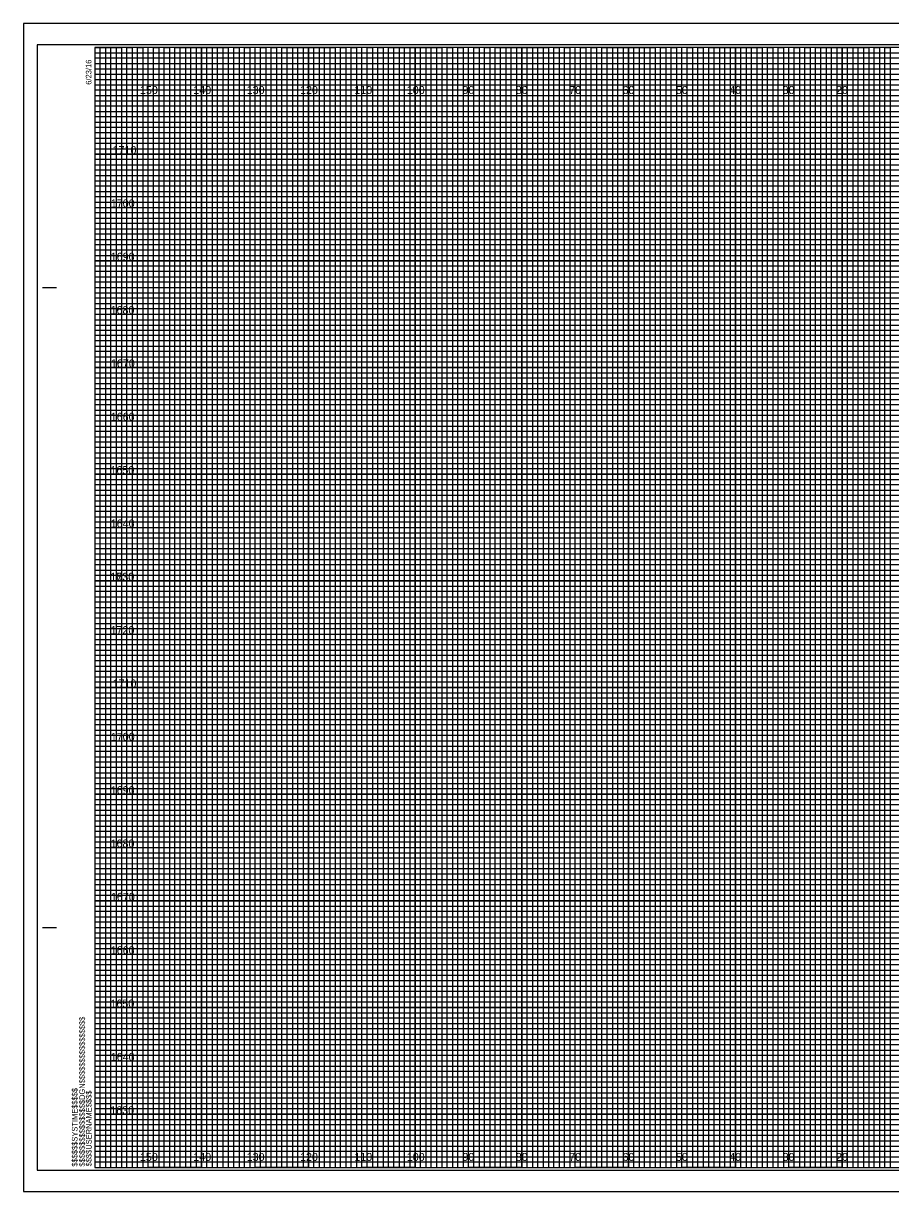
# Model space of a CAD drawing. Extents: x -419 to 4739, y -630 to 13534.
# Drawn here: x 1539.8 to 1702.3, y 415.2 to 634.2 of the extents above; entities that cross this region are included whole.
import ezdxf

# ---------------------------------------------------------------- set-up
doc = ezdxf.new("R2010")
doc.units = 0
for name, color, linetype in [('Old_Level_62', 7, 'Continuous'), ('Pattern 1', 7, 'Continuous'), ('Pattern 18', 7, 'Continuous'), ('Pattern 4', 7, 'Continuous'), ('Pattern 5', 7, 'Continuous'), ('Prop Dimension', 7, 'Continuous'), ('Prop Horizontal Alignment', 7, 'Continuous'), ('Raster_Level_0', 7, 'Continuous'), ('Scratch_Level_0', 7, 'Continuous'), ('Scratch_Level_3', 7, 'Continuous'), ('Scratch_Level_5', 7, 'Continuous')]:
    doc.layers.add(name, color=color, linetype=linetype)

msp = doc.modelspace()

# ---------------------------------------------------------------- linework, layer by layer
at = {"layer": 'Old_Level_62'}
for p, q in [((1543.4, 584.66), (1545.9, 584.66)), ((1543.5, 584.66), (1546, 584.66)), ((1543.4, 464.66), (1545.9, 464.66)), ((1543.5, 464.66), (1546, 464.66)), ((1553.2, 419.66), (1553.2, 419.66)), ((1553.2, 419.66), (1553.2, 419.66)), ((1553.2, 419.66), (1553.2, 419.66)), ((1553.2, 419.66), (1553.2, 419.66)), ((1553.2, 419.66), (1553.2, 419.66)), ((1553.2, 419.66), (1553.2, 419.66)), ((1553.2, 419.66), (1553.2, 419.66))]:
    msp.add_line(p, q, dxfattribs=at)
msp.add_lwpolyline([(1873.2, 629.66), (1553.2, 629.66), (1553.2, 419.66), (1873.2, 419.66)], close=True, dxfattribs=at)
at = {"layer": 'Pattern 18'}
msp.add_lwpolyline([(1539.8, 415.16), (1876.5, 415.16), (1876.5, 634.16), (1539.8, 634.16)], close=True, dxfattribs=at)
at = {"layer": 'Pattern 4'}
for p, q in [((1553.2, 628.66), (1813.2, 628.66)), ((1813.2, 627.64), (1553.2, 627.64)), ((1553.2, 627.64), (1553.2, 626.66)), ((1553.2, 626.66), (1813.2, 626.66)), ((1813.2, 625.55), (1553.2, 625.55)), ((1553.2, 625.55), (1553.2, 623.66)), ((1553.2, 623.66), (1873.2, 623.66))]:
    msp.add_line(p, q, dxfattribs=at)
for points in [[(1553.2, 622.66), (1823.2, 622.66), (1873.2, 622.66), (1873.2, 621.66), (1553.2, 621.66)], [(1553.2, 620.66), (1873.2, 620.66), (1873.2, 618.66), (1553.2, 618.66)], [(1553.2, 617.66), (1873.2, 617.66), (1873.2, 616.66), (1553.2, 616.64)], [(1553.2, 615.66), (1873.2, 615.66), (1873.2, 613.66), (1553.2, 613.66)], [(1553.2, 612.66), (1873.2, 612.66), (1873.2, 611.66), (1553.2, 611.66)], [(1553.2, 610.66), (1873.2, 610.66), (1873.2, 608.66), (1553.2, 608.66)], [(1553.2, 607.66), (1873.2, 607.66), (1873.2, 606.66), (1553.2, 606.66)], [(1553.2, 605.66), (1873.2, 605.66), (1873.2, 603.66), (1553.2, 603.66)], [(1553.2, 602.66), (1873.2, 602.66), (1873.2, 601.66), (1553.2, 601.66)], [(1553.2, 600.66), (1873.2, 600.66), (1873.2, 598.66), (1553.2, 598.66)], [(1553.2, 597.66), (1873.2, 597.66), (1873.2, 596.66), (1553.2, 596.66)], [(1553.2, 595.66), (1873.2, 595.66), (1873.2, 593.61), (1873.2, 592.66), (1873.2, 591.66), (1553.2, 591.66)], [(1553.2, 593.66), (1873.2, 593.66), (1873.2, 592.66), (1553.2, 592.66)], [(1553.2, 590.66), (1873.2, 590.66), (1873.2, 588.66), (1553.2, 588.69)], [(1553.2, 588.69), (1873.2, 588.66), (1873.2, 587.66), (1553.2, 587.66)], [(1553.2, 586.66), (1873.2, 586.66), (1873.2, 585.66), (1553.2, 585.66)], [(1553.2, 583.66), (1873.2, 583.66), (1873.2, 582.66), (1553.2, 582.66)], [(1553.2, 581.66), (1873.2, 581.66), (1873.2, 580.66), (1553.2, 580.66)], [(1553.13, 578.55), (1873.2, 578.55), (1873.2, 577.54), (1553.13, 577.54)], [(1553.2, 576.66), (1873.2, 576.66), (1873.2, 575.66), (1553.2, 575.66)], [(1553.2, 573.66), (1873.2, 573.66), (1873.2, 572.66), (1553.2, 572.66)], [(1553.2, 571.66), (1873.2, 571.66), (1873.2, 570.66), (1553.2, 570.66)], [(1553.2, 568.66), (1873.2, 568.66), (1873.2, 567.66), (1553.2, 567.66)], [(1553.2, 566.66), (1873.2, 566.66), (1873.2, 565.66), (1553.2, 565.66)], [(1553.2, 563.66), (1873.2, 563.66), (1873.2, 562.66), (1553.2, 562.66)], [(1553.2, 561.66), (1873.2, 561.66), (1873.2, 560.66), (1553.2, 560.66)], [(1553.2, 558.66), (1873.2, 558.66), (1873.19, 557.64), (1553.2, 557.66)], [(1553.2, 556.66), (1873.2, 556.66), (1873.2, 555.66), (1553.2, 555.66)], [(1553.2, 553.66), (1873.2, 553.66), (1873.2, 552.66), (1553.2, 552.66)], [(1553.2, 551.66), (1873.2, 551.66), (1873.2, 550.66), (1553.2, 550.66)], [(1553.2, 548.66), (1873.2, 548.66), (1873.2, 547.66), (1553.2, 547.66)], [(1553.2, 546.66), (1873.2, 546.66), (1873.2, 545.66), (1553.2, 545.66)], [(1553.2, 543.66), (1873.2, 543.66), (1873.2, 542.66), (1553.2, 542.66)], [(1553.2, 541.66), (1873.2, 541.66), (1873.2, 540.66), (1553.2, 540.66)], [(1553.2, 538.66), (1873.2, 538.66), (1873.2, 537.66), (1553.2, 537.66)], [(1553.2, 536.65), (1873.27, 536.57), (1873.2, 535.66), (1553.2, 535.66)], [(1553.2, 533.66), (1873.2, 533.66), (1873.2, 532.66), (1553.2, 532.66)], [(1553.2, 531.66), (1873.2, 531.66), (1873.2, 530.66), (1553.2, 530.66)], [(1553.2, 528.66), (1873.2, 528.66), (1873.2, 527.66), (1553.2, 527.66)], [(1553.2, 526.66), (1873.2, 526.66), (1873.2, 525.66), (1553.2, 525.66)], [(1553.2, 523.66), (1873.2, 523.66), (1873.2, 522.66), (1553.2, 522.66)], [(1553.2, 521.66), (1873.2, 521.66), (1873.2, 520.66), (1553.2, 520.66)], [(1553.2, 518.66), (1873.2, 518.66), (1873.2, 517.66), (1553.2, 517.66)], [(1553.2, 516.66), (1873.2, 516.66), (1873.2, 515.66), (1553.2, 515.66)], [(1553.2, 513.66), (1873.2, 513.66), (1873.2, 512.66), (1553.2, 512.66)], [(1553.2, 511.66), (1873.2, 511.66), (1873.2, 510.66), (1553.2, 510.66)], [(1553.2, 508.66), (1873.2, 508.66), (1873.2, 507.66), (1553.2, 507.66)], [(1553.2, 506.66), (1873.2, 506.66), (1873.2, 505.66), (1553.2, 505.66)], [(1553.2, 503.66), (1873.2, 503.66), (1873.2, 502.66), (1553.2, 502.66)], [(1553.2, 501.66), (1873.2, 501.66), (1873.2, 500.66), (1553.2, 500.66)], [(1553.2, 498.66), (1873.2, 498.66), (1873.19, 497.64), (1553.2, 497.66)], [(1553.2, 496.66), (1873.2, 496.66), (1873.2, 495.66), (1553.2, 495.66)], [(1553.2, 493.66), (1873.2, 493.66), (1873.2, 492.66), (1553.2, 492.66)], [(1553.2, 491.66), (1873.2, 491.66), (1873.2, 490.66), (1553.2, 490.66)], [(1553.2, 488.66), (1873.2, 488.66), (1873.2, 487.66), (1553.2, 487.66)], [(1553.2, 486.66), (1873.2, 486.66), (1873.2, 485.66), (1553.2, 485.66)], [(1553.2, 483.66), (1873.2, 483.66), (1873.2, 482.66), (1553.2, 482.66)], [(1553.2, 481.66), (1873.2, 481.66), (1873.2, 480.66), (1553.2, 480.66)], [(1553.2, 478.66), (1873.2, 478.66), (1873.2, 477.66), (1553.2, 477.66)], [(1553.2, 476.65), (1873.27, 476.57), (1873.2, 475.66), (1553.2, 475.66)], [(1553.2, 473.66), (1873.2, 473.66), (1873.2, 472.66), (1553.2, 472.66)], [(1553.2, 471.66), (1873.2, 471.66), (1873.2, 470.66), (1553.2, 470.66)], [(1553.2, 468.66), (1873.2, 468.66), (1873.2, 467.66), (1553.2, 467.66)], [(1553.2, 466.66), (1873.2, 466.66), (1873.2, 465.66), (1553.2, 465.66)], [(1553.2, 463.66), (1873.2, 463.66), (1873.2, 462.66), (1553.2, 462.66)], [(1553.2, 461.66), (1873.2, 461.66), (1873.2, 460.66), (1553.2, 460.66)], [(1553.2, 458.66), (1873.2, 458.66), (1873.2, 457.66), (1553.2, 457.66)], [(1553.2, 456.66), (1873.2, 456.66), (1873.2, 455.66), (1553.2, 455.66)], [(1553.2, 453.66), (1873.2, 453.66), (1873.2, 452.66), (1553.2, 452.66)], [(1553.2, 451.66), (1873.2, 451.66), (1873.2, 450.66), (1553.2, 450.66)], [(1553.2, 448.66), (1873.2, 448.66), (1873.2, 447.66), (1553.2, 447.66)], [(1553.2, 446.66), (1873.2, 446.66), (1873.2, 445.66), (1553.2, 445.66)], [(1553.2, 443.66), (1873.2, 443.66), (1873.2, 442.66), (1553.2, 442.66)], [(1553.2, 441.66), (1873.2, 441.66), (1873.2, 440.66), (1553.2, 440.66)], [(1553.2, 438.66), (1873.2, 438.66), (1873.2, 437.66), (1553.2, 437.66)], [(1553.2, 436.66), (1873.2, 436.66), (1873.2, 435.66), (1553.2, 435.66)], [(1553.2, 433.66), (1873.2, 433.66), (1873.2, 432.66), (1553.2, 432.66)], [(1553.2, 431.66), (1873.2, 431.66), (1873.2, 430.66), (1553.2, 430.66)], [(1553.2, 428.66), (1873.2, 428.66), (1873.2, 427.66), (1553.2, 427.66)], [(1553.2, 426.66), (1873.2, 426.66), (1873.2, 425.66), (1553.2, 425.66)], [(1553.2, 423.66), (1873.2, 423.66), (1873.2, 422.66), (1553.2, 422.66)], [(1553.2, 421.66), (1873.2, 421.66), (1873.2, 420.66), (1553.2, 420.66)]]:
    msp.add_lwpolyline(points, dxfattribs=at)
at = {"layer": 'Pattern 5'}
for p, q in [((1876.5, 634.16), (1539.8, 634.16)), ((1539.8, 634.16), (1539.8, 415.16)), ((1539.8, 415.16), (1876.5, 415.16))]:
    msp.add_line(p, q, dxfattribs=at)
at = {"layer": 'Prop Dimension'}
for points in [[(1553.2, 419.66), (1554.2, 419.66), (1554.2, 629.66), (1555.2, 629.66), (1555.2, 419.66)], [(1555.2, 419.66), (1556.2, 419.66), (1556.2, 629.66), (1557.2, 629.66), (1557.2, 419.66)], [(1558.2, 419.66), (1559.2, 419.66), (1559.2, 629.66), (1560.2, 629.66), (1560.2, 419.66)], [(1560.2, 419.66), (1561.2, 419.66), (1561.2, 629.66), (1562.2, 629.66), (1562.2, 419.66)], [(1563.2, 419.66), (1564.2, 419.66), (1564.2, 629.66), (1565.2, 629.66), (1565.2, 419.66)], [(1565.2, 419.66), (1566.2, 419.66), (1566.2, 629.66), (1567.2, 629.66), (1567.2, 419.66)], [(1568.2, 419.66), (1569.2, 419.66), (1569.2, 629.66), (1570.2, 629.66), (1570.2, 419.66)], [(1570.2, 419.66), (1571.2, 419.66), (1571.2, 629.66), (1572.2, 629.66), (1572.2, 419.66)], [(1573.2, 419.66), (1574.2, 419.66), (1574.2, 629.66), (1575.2, 629.66), (1575.2, 419.66)], [(1575.2, 419.66), (1576.2, 419.66), (1576.2, 629.66), (1577.2, 629.66), (1577.2, 419.66)], [(1578.2, 419.66), (1579.2, 419.66), (1579.2, 629.66), (1580.2, 629.66), (1580.2, 419.66)], [(1580.2, 419.66), (1581.2, 419.66), (1581.2, 629.66), (1582.2, 629.66), (1582.2, 419.66)], [(1583.2, 419.66), (1584.2, 419.66), (1584.2, 629.66), (1585.2, 629.66), (1585.2, 419.66)], [(1585.2, 419.66), (1586.2, 419.66), (1586.2, 629.66), (1587.2, 629.66), (1587.2, 419.66)], [(1588.2, 419.66), (1589.2, 419.66), (1589.2, 629.66), (1590.2, 629.66), (1590.2, 419.66)], [(1590.2, 419.66), (1591.2, 419.66), (1591.2, 629.66), (1592.2, 629.66), (1592.2, 419.66)], [(1593.2, 419.66), (1594.2, 419.66), (1594.2, 629.66), (1595.2, 629.66), (1595.2, 419.66)], [(1595.2, 419.66), (1596.2, 419.66), (1596.2, 629.66), (1597.2, 629.66), (1597.2, 419.66)], [(1598.2, 419.66), (1599.2, 419.66), (1599.2, 629.66), (1600.2, 629.66), (1600.2, 419.66)], [(1600.2, 419.66), (1601.2, 419.66), (1601.2, 629.66), (1602.2, 629.66), (1602.2, 419.66)], [(1603.2, 419.66), (1604.2, 419.66), (1604.2, 629.66), (1605.2, 629.66), (1605.2, 419.66)], [(1605.2, 419.66), (1606.2, 419.66), (1606.2, 629.66), (1607.2, 629.66), (1607.2, 419.66)], [(1608.2, 419.66), (1609.2, 419.66), (1609.2, 629.66), (1610.2, 629.66), (1610.2, 419.66)], [(1610.2, 419.66), (1611.2, 419.66), (1611.2, 629.66), (1612.2, 629.66), (1612.2, 419.66)], [(1613.2, 419.66), (1614.2, 419.66), (1614.2, 629.66), (1615.2, 629.66), (1615.2, 419.66)], [(1615.2, 419.66), (1616.2, 419.66), (1616.2, 629.66), (1617.2, 629.66), (1617.2, 419.66)], [(1618.2, 419.66), (1619.2, 419.66), (1619.2, 629.66), (1620.2, 629.66), (1620.2, 419.66)], [(1620.2, 419.66), (1621.2, 419.66), (1621.2, 629.66), (1622.2, 629.66), (1622.2, 419.66)], [(1623.2, 419.66), (1624.2, 419.66), (1624.2, 629.66), (1625.2, 629.66), (1625.2, 419.66)], [(1625.2, 419.66), (1626.2, 419.66), (1626.2, 629.66), (1627.2, 629.66), (1627.2, 419.66)], [(1628.2, 419.66), (1629.2, 419.66), (1629.2, 629.66), (1630.2, 629.66), (1630.2, 419.66)], [(1630.2, 419.66), (1631.2, 419.66), (1631.2, 629.66), (1632.2, 629.66), (1632.2, 419.66)], [(1633.2, 419.66), (1634.2, 419.66), (1634.2, 629.66), (1635.2, 629.66), (1635.2, 419.66)], [(1635.2, 419.66), (1636.2, 419.66), (1636.2, 629.66), (1637.2, 629.66), (1637.2, 419.66)], [(1638.2, 419.66), (1639.2, 419.66), (1639.2, 629.66), (1640.2, 629.66), (1640.2, 419.66)], [(1640.2, 419.66), (1641.2, 419.66), (1641.2, 629.66), (1642.2, 629.66), (1642.2, 419.66)], [(1643.2, 419.66), (1644.2, 419.66), (1644.2, 629.66), (1645.2, 629.66), (1645.2, 419.66)], [(1645.2, 419.66), (1646.2, 419.66), (1646.2, 629.66), (1647.2, 629.66), (1647.2, 419.66)], [(1648.2, 419.66), (1649.2, 419.66), (1649.2, 629.66), (1650.2, 629.66), (1650.2, 419.66)], [(1650.2, 419.66), (1651.2, 419.66), (1651.2, 629.66), (1652.2, 629.66), (1652.2, 419.66)], [(1653.2, 419.66), (1654.2, 419.66), (1654.2, 629.66), (1655.2, 629.66), (1655.2, 419.66)], [(1655.2, 419.66), (1656.2, 419.66), (1656.2, 629.66), (1657.2, 629.66), (1657.2, 419.66)], [(1658.2, 419.66), (1659.2, 419.66), (1659.2, 629.66), (1660.2, 629.66), (1660.2, 419.66)], [(1660.2, 419.66), (1661.2, 419.66), (1661.2, 629.66), (1662.2, 629.66), (1662.2, 419.66)], [(1663.2, 419.66), (1664.2, 419.66), (1664.2, 629.66), (1665.2, 629.66), (1665.2, 419.66)], [(1665.2, 419.66), (1666.2, 419.66), (1666.2, 629.66), (1667.2, 629.66), (1667.2, 419.66)], [(1668.2, 419.66), (1669.2, 419.66), (1669.2, 629.66), (1670.2, 629.66), (1670.2, 419.66)], [(1670.2, 419.66), (1671.2, 419.66), (1671.2, 629.66), (1672.2, 629.66), (1672.2, 419.66)], [(1673.2, 419.66), (1674.2, 419.66), (1674.2, 629.66), (1675.2, 629.66), (1675.2, 419.66)], [(1675.2, 419.66), (1676.2, 419.66), (1676.2, 629.66), (1677.2, 629.66), (1677.2, 419.66)], [(1678.2, 419.66), (1679.2, 419.66), (1679.2, 629.66), (1680.2, 629.66), (1680.2, 419.66)], [(1680.2, 419.66), (1681.2, 419.66), (1681.2, 629.66), (1682.2, 629.66), (1682.2, 419.66)], [(1683.2, 419.66), (1684.2, 419.66), (1684.2, 629.66), (1685.2, 629.66), (1685.2, 419.66)], [(1685.2, 419.66), (1686.2, 419.66), (1686.2, 629.66), (1687.2, 629.66), (1687.2, 419.66)], [(1688.2, 419.66), (1689.2, 419.66), (1689.2, 629.66), (1690.2, 629.66), (1690.2, 419.66)], [(1690.2, 419.66), (1691.2, 419.66), (1691.2, 629.66), (1692.2, 629.66), (1692.2, 419.66)], [(1693.2, 419.66), (1694.2, 419.66), (1694.2, 629.66), (1695.2, 629.66), (1695.2, 419.66)], [(1695.2, 419.66), (1696.2, 419.66), (1696.2, 629.66), (1697.2, 629.66), (1697.2, 419.66)], [(1698.2, 419.66), (1699.2, 419.66), (1699.2, 629.66), (1700.2, 629.66), (1700.2, 419.66)], [(1700.2, 419.66), (1701.2, 419.66), (1701.2, 629.66), (1702.2, 629.66), (1702.2, 419.66)]]:
    msp.add_lwpolyline(points, dxfattribs=at)
at = {"layer": 'Prop Horizontal Alignment'}
for points in [[(1553.2, 629.66), (1558.2, 629.66), (1558.2, 419.66), (1568.2, 419.66), (1568.2, 629.66), (1578.2, 629.66), (1578.2, 419.66), (1588.2, 419.66), (1588.2, 629.66), (1598.2, 629.66), (1598.2, 419.66), (1608.2, 419.66), (1608.2, 629.66), (1618.2, 629.66), (1618.2, 419.66), (1628.2, 419.66), (1628.2, 629.66), (1638.2, 629.66), (1638.2, 419.66), (1648.2, 419.66), (1648.2, 629.66), (1658.2, 629.66), (1658.2, 419.66), (1668.2, 419.66), (1668.2, 629.66), (1678.2, 629.66), (1678.2, 419.66), (1688.2, 419.66), (1688.2, 629.66), (1698.2, 629.66), (1698.2, 419.66), (1708.2, 419.66)], [(1553.2, 624.66), (1828.2, 624.66)], [(1553.2, 604.66), (1873.2, 604.66), (1873.2, 614.66), (1553.2, 614.66)], [(1553.2, 584.66), (1873.2, 584.66), (1873.2, 594.66), (1553.2, 594.66)], [(1553.2, 564.66), (1873.2, 564.66), (1873.2, 574.66), (1553.2, 574.66)], [(1553.2, 544.66), (1873.2, 544.66), (1873.2, 554.66), (1553.2, 554.66)], [(1553.2, 524.66), (1873.2, 524.66), (1873.2, 534.66), (1553.2, 534.66)], [(1553.2, 504.66), (1873.2, 504.66), (1873.2, 514.66), (1553.2, 514.66)], [(1553.2, 484.66), (1873.2, 484.66), (1873.2, 494.66), (1553.2, 494.66)], [(1553.2, 464.66), (1873.2, 464.66), (1873.2, 474.66), (1553.2, 474.66)], [(1553.2, 444.66), (1873.2, 444.66), (1873.2, 454.66), (1553.2, 454.66)], [(1553.2, 424.66), (1873.2, 424.66), (1873.2, 434.66), (1553.2, 434.66)]]:
    msp.add_lwpolyline(points, dxfattribs=at)
at = {"layer": 'Scratch_Level_0'}
for p, q in [((1563.2, 419.66), (1563.2, 629.66)), ((1573.2, 419.66), (1573.2, 629.66)), ((1583.2, 419.66), (1583.2, 629.66)), ((1593.2, 419.66), (1593.2, 629.66)), ((1603.2, 419.66), (1603.2, 629.66)), ((1613.2, 419.66), (1613.2, 629.66)), ((1623.2, 419.66), (1623.2, 629.66)), ((1633.2, 419.66), (1633.2, 629.66)), ((1643.2, 419.66), (1643.2, 629.66)), ((1653.2, 419.66), (1653.2, 629.66)), ((1663.2, 419.66), (1663.2, 629.66)), ((1673.2, 419.66), (1673.2, 629.66)), ((1683.2, 419.66), (1683.2, 629.66)), ((1693.2, 419.66), (1693.2, 629.66)), ((1553.2, 619.66), (1873.2, 619.66)), ((1553.2, 609.66), (1873.2, 609.66)), ((1553.2, 599.66), (1873.2, 599.66)), ((1553.2, 589.66), (1873.2, 589.66)), ((1553.2, 579.66), (1873.2, 579.66)), ((1553.2, 569.66), (1873.2, 569.66)), ((1553.2, 559.66), (1873.2, 559.66)), ((1553.2, 549.66), (1873.2, 549.66)), ((1553.2, 539.66), (1873.2, 539.66)), ((1553.2, 529.66), (1873.2, 529.66)), ((1553.2, 519.66), (1873.2, 519.66)), ((1553.2, 509.66), (1873.2, 509.66)), ((1553.2, 499.66), (1873.2, 499.66)), ((1553.2, 489.66), (1873.2, 489.66)), ((1553.2, 479.66), (1873.2, 479.66)), ((1553.2, 469.66), (1873.2, 469.66)), ((1553.2, 459.66), (1873.2, 459.66)), ((1553.2, 449.66), (1873.2, 449.66)), ((1553.2, 439.66), (1873.2, 439.66)), ((1553.2, 429.66), (1873.2, 429.66))]:
    msp.add_line(p, q, dxfattribs=at)
at = {"layer": 'Scratch_Level_3'}
for p, q in [((1563.2, 629.66), (1553.2, 629.66)), ((1563.2, 419.66), (1563.2, 629.66)), ((1583.2, 629.66), (1573.2, 629.66)), ((1573.2, 629.66), (1573.2, 419.66)), ((1583.2, 419.66), (1583.2, 629.66)), ((1603.2, 629.66), (1593.2, 629.66)), ((1593.2, 629.66), (1593.2, 419.66)), ((1603.2, 419.66), (1603.2, 629.66)), ((1623.2, 629.66), (1613.2, 629.66)), ((1613.2, 629.66), (1613.2, 419.66)), ((1623.2, 419.66), (1623.2, 629.66)), ((1643.2, 629.66), (1633.2, 629.66)), ((1633.2, 629.66), (1633.2, 419.66)), ((1643.2, 419.66), (1643.2, 629.66)), ((1663.2, 629.66), (1653.2, 629.66)), ((1653.2, 629.66), (1653.2, 419.66)), ((1663.2, 419.66), (1663.2, 629.66)), ((1683.2, 629.66), (1673.2, 629.66)), ((1673.2, 629.66), (1673.2, 419.66)), ((1683.2, 419.66), (1683.2, 629.66)), ((1703.2, 629.66), (1693.2, 629.66)), ((1693.2, 629.66), (1693.2, 419.66)), ((1573.2, 419.66), (1563.2, 419.66)), ((1593.2, 419.66), (1583.2, 419.66)), ((1613.2, 419.66), (1603.2, 419.66)), ((1633.2, 419.66), (1623.2, 419.66)), ((1653.2, 419.66), (1643.2, 419.66)), ((1673.2, 419.66), (1663.2, 419.66)), ((1693.2, 419.66), (1683.2, 419.66))]:
    msp.add_line(p, q, dxfattribs=at)
for points in [[(1553.2, 619.66), (1873.2, 619.66), (1873.2, 609.66), (1553.2, 609.66)], [(1553.2, 599.66), (1873.2, 599.66), (1873.2, 589.66), (1553.2, 589.66)], [(1553.2, 579.66), (1873.2, 579.66), (1873.2, 569.66), (1553.2, 569.66)], [(1553.2, 559.66), (1873.2, 559.66), (1873.2, 549.66), (1553.2, 549.66)], [(1553.2, 539.66), (1873.2, 539.66), (1873.2, 529.66), (1553.2, 529.66)], [(1553.2, 519.66), (1873.2, 519.66), (1873.2, 509.66), (1553.2, 509.66)], [(1553.2, 499.66), (1873.2, 499.66), (1873.2, 489.66), (1553.2, 489.66)], [(1553.2, 479.66), (1873.2, 479.66), (1873.2, 469.66), (1553.2, 469.66)], [(1553.2, 459.66), (1873.2, 459.66), (1873.2, 449.66), (1553.2, 449.66)], [(1553.2, 439.66), (1873.2, 439.66), (1873.2, 429.66), (1553.2, 429.66)]]:
    msp.add_lwpolyline(points, dxfattribs=at)
at = {"layer": 'Scratch_Level_5'}
msp.add_lwpolyline([(1542.4, 419.16), (1875.6, 419.16), (1875.6, 630.16), (1542.4, 630.16)], close=True, dxfattribs=at)

# ---------------------------------------------------------------- texts
at = {"layer": 'Old_Level_62'}
for s, p in [('6/23/16', (1552.55, 622.66)), ('$$$$$$$$$$$$$$$$DGN$$$$$$$$$$$$$$$$', (1551.32, 419.84)), ('$$$$$$SYSTIME$$$$$', (1549.94, 419.84)), ('$$$$USERNAME$$$$', (1552.58, 419.89))]:
    msp.add_text(s, height=1.05, rotation=90, dxfattribs=at).set_placement(p)
at = {"layer": 'Pattern 1'}
for s, p in [('1710', (1556.51, 609.66)), ('1700', (1556.18, 599.66)), ('1690', (1556.17, 589.66)), ('1680', (1556.14, 579.66)), ('1670', (1556.2, 569.66)), ('1660', (1556.17, 559.66)), ('1650', (1556.12, 549.66)), ('1640', (1556.17, 539.66)), ('1630', (1556.08, 529.66)), ('1730', (1556.12, 529.66)), ('1720', (1556.13, 519.66)), ('1710', (1556.51, 509.66)), ('1700', (1556.18, 499.66)), ('1690', (1556.17, 489.66)), ('1680', (1556.14, 479.66)), ('1670', (1556.2, 469.66)), ('1660', (1556.17, 459.66)), ('1650', (1556.12, 449.66)), ('1640', (1556.17, 439.66)), ('1630', (1556.08, 429.66))]:
    msp.add_text(s, height=1.5, dxfattribs=at).set_placement(p)
at = {"layer": 'Raster_Level_0'}
for s, p in [('150', (1561.64, 620.91)), ('140', (1571.64, 620.91)), ('130', (1581.64, 620.91)), ('120', (1591.64, 620.91)), ('110', (1601.82, 620.91)), ('100', (1611.64, 620.91)), ('90', (1622.06, 620.91)), ('80', (1632.06, 620.91)), ('70', (1642.06, 620.91)), ('60', (1652.06, 620.91)), ('50', (1662.06, 620.91)), ('40', (1672.06, 620.91)), ('30', (1682.06, 620.91)), ('20', (1692.06, 620.91)), ('150', (1561.64, 420.91)), ('140', (1571.64, 420.91)), ('130', (1581.64, 420.91)), ('120', (1591.64, 420.91)), ('110', (1601.82, 420.91)), ('100', (1611.64, 420.91)), ('90', (1622.06, 420.91)), ('80', (1632.06, 420.91)), ('70', (1642.06, 420.91)), ('60', (1652.06, 420.91)), ('50', (1662.06, 420.91)), ('40', (1672.06, 420.91)), ('30', (1682.06, 420.91)), ('20', (1692.06, 420.91))]:
    msp.add_text(s, height=1.5, dxfattribs=at).set_placement(p)

doc.saveas('drawing.dxf')
